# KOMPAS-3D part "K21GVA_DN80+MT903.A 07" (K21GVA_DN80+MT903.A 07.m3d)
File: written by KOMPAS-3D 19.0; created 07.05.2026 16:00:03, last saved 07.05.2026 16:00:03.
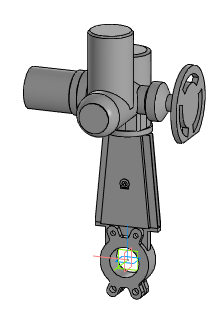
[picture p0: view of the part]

Document properties: Автор: Энергия; Полное имя файла: ..\K21GVA_DN50-DN1000+MT903.A\K21GVA_DN80+MT903.A 07.a3d

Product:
- Part/product: K21GVA_DN80+MT903.A 07
    Масса: 74.3784

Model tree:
1. Операция без истории:1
